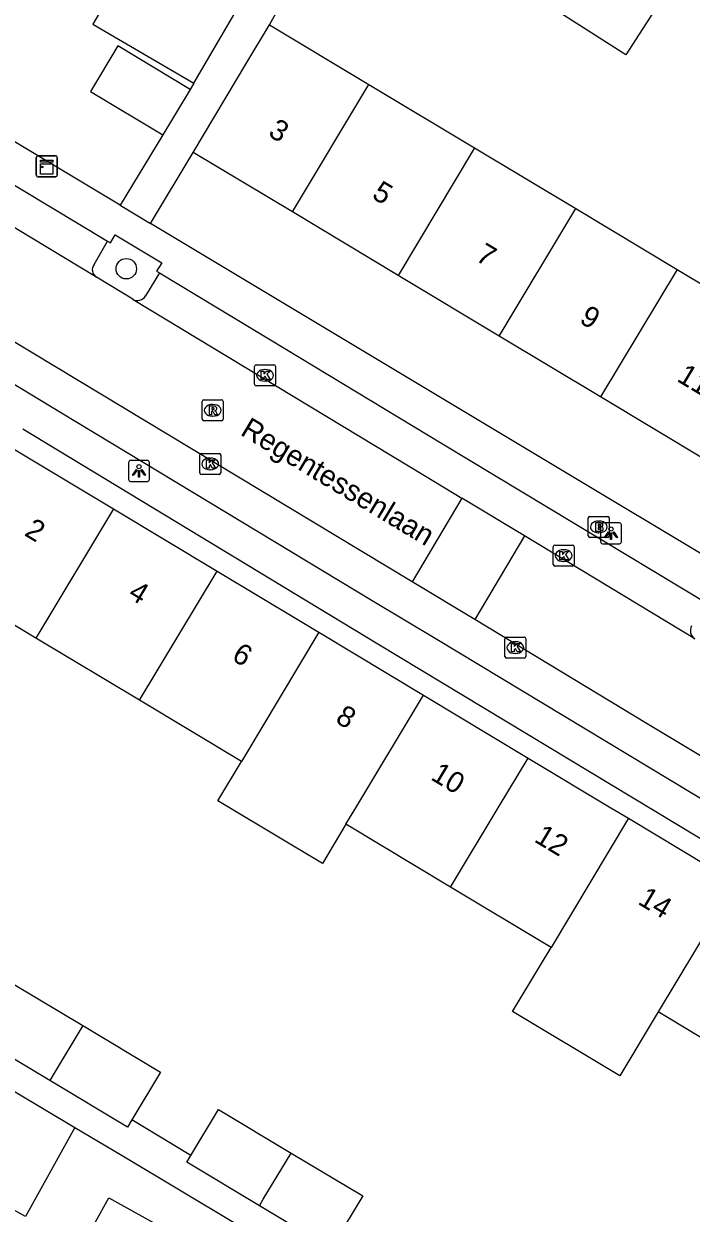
# Model space of a CAD drawing. Extents: x 160107 to 160928, y 382056 to 382918.
# Drawn here: x 160352.1 to 160383.9, y 382230.6 to 382287.4 of the extents above; entities that cross this region are included whole.
import ezdxf

# ---------------------------------------------------------------- set-up
doc = ezdxf.new("R2010")
doc.units = 0
for name, color, linetype in [('IMGEO_Boom', 7, 'Continuous'), ('IMGEO_Brandkraan', 7, 'Continuous'), ('IMGEO_Kast', 7, 'Continuous'), ('IMGEO_Kolk', 7, 'Continuous'), ('IMGEO_Lichtpunt', 7, 'Continuous'), ('IMGEO_Openbare_ruimte_label', 7, 'Continuous'), ('IMGEO_Pand', 7, 'Continuous'), ('IMGEO_Pand_nummerreeks', 7, 'Continuous'), ('IMGEO_Parkeervlak_open', 7, 'Continuous'), ('IMGEO_Rijbaan_lokaal_open', 7, 'Continuous'), ('IMGEO_Rioolput', 7, 'Continuous'), ('IMGEO_Voetpad_open', 7, 'Continuous')]:
    doc.layers.add(name, color=color, linetype=linetype)

msp = doc.modelspace()

# ---------------------------------------------------------------- linework, layer by layer
at = {"layer": 'IMGEO_Boom'}
msp.add_circle((160356.952, 382275.745), 0.489, dxfattribs=at)
at = {"layer": 'IMGEO_Brandkraan'}
for p, q in [((160379.024, 382262.989), (160379.024, 382263.841)), ((160379.099, 382263.915), (160379.951, 382263.915)), ((160380.025, 382263.841), (160380.025, 382262.989)), ((160379.512, 382263.695), (160379.537, 382263.695)), ((160379.951, 382262.915), (160379.099, 382262.915)), ((160379.535, 382263.135), (160379.51, 382263.135))]:
    msp.add_line(p, q, dxfattribs=at)
for points in [[(160379.024, 382262.989), (160379.024, 382263.841)], [(160379.099, 382263.915), (160379.951, 382263.915)], [(160380.025, 382263.841), (160380.025, 382262.989)], [(160379.372, 382263.615), (160379.372, 382263.215), (160379.585, 382263.215)], [(160379.603, 382263.615), (160379.372, 382263.615)], [(160379.551, 382263.534), (160379.497, 382263.534), (160379.497, 382263.458)], [(160379.497, 382263.458), (160379.55, 382263.458)], [(160379.559, 382263.382), (160379.497, 382263.382), (160379.497, 382263.301)], [(160379.497, 382263.301), (160379.559, 382263.301)], [(160379.951, 382262.915), (160379.099, 382262.915)]]:
    msp.add_lwpolyline(points, dxfattribs=at)
for centre, radius, start, end in [((160379.101, 382263.839), 0.0765, 91.552, 178.448), ((160379.101, 382263.839), 0.0765, 91.552, 178.448), ((160379.949, 382263.839), 0.0765, 1.552, 88.448), ((160379.949, 382263.839), 0.0765, 1.552, 88.448), ((160379.552, 382263.496), 0.0379, 267.8285, 90.9355), ((160379.56, 382263.341), 0.0404, 269.8759, 90.5077), ((160379.591, 382263.466), 0.251, 268.6676, 293.5347), ((160379.607, 382263.47), 0.145, 59.4692, 91.5367), ((160379.632, 382263.517), 0.0922, 285.5137, 58.1501), ((160379.637, 382263.325), 0.105, 301.3115, 78.989), ((160379.101, 382262.991), 0.0765, 181.552, 268.448), ((160379.101, 382262.991), 0.0765, 181.552, 268.448), ((160379.949, 382262.991), 0.0765, 271.552, 358.448), ((160379.949, 382262.991), 0.0765, 271.552, 358.448)]:
    msp.add_arc(centre, radius, start, end, dxfattribs=at)
for centre, major_axis, ratio, start_param, end_param in [((160379.511, 382263.415), (-0.387, 0.002), 0.722429, 4.712389, 7.853982), ((160379.536, 382263.415), (-0.39, 0.002), 0.717154, 1.570796, 4.712389)]:
    msp.add_ellipse(centre, major_axis=major_axis, ratio=ratio, start_param=start_param, end_param=end_param, dxfattribs=at)
at = {"layer": 'IMGEO_Kast'}
for p, q in [((160352.654, 382280.212), (160352.654, 382281.053)), ((160352.654, 382281.053), (160352.654, 382280.212)), ((160352.729, 382281.137), (160353.57, 382281.137)), ((160353.57, 382281.137), (160352.729, 382281.137)), ((160353.654, 382281.062), (160353.654, 382280.221)), ((160353.654, 382280.221), (160353.654, 382281.062)), ((160353.579, 382280.137), (160352.738, 382280.137)), ((160352.738, 382280.137), (160353.579, 382280.137))]:
    msp.add_line(p, q, dxfattribs=at)
for points in [[(160352.849, 382280.927), (160353.449, 382280.927), (160353.449, 382280.842), (160352.849, 382280.842), (160352.849, 382280.927)], [(160352.849, 382280.752), (160353.449, 382280.752), (160353.449, 382280.263), (160352.849, 382280.263), (160352.849, 382280.752)]]:
    msp.add_lwpolyline(points, dxfattribs=at)
msp.add_circle((160352.933, 382280.601), 0.0377, dxfattribs=at)
for centre, start, end in [((160352.732, 382281.059), 92.4484, 184.2845), ((160352.732, 382281.059), 92.4484, 184.2845), ((160353.576, 382281.059), 2.4484, 94.2845), ((160353.576, 382281.059), 2.4484, 94.2845), ((160352.732, 382280.215), 182.4484, 274.2845), ((160352.732, 382280.215), 182.4484, 274.2845), ((160353.576, 382280.215), 272.4484, 4.2845), ((160353.576, 382280.215), 272.4484, 4.2845)]:
    msp.add_arc(centre, 0.0779, start, end, dxfattribs=at)
at = {"layer": 'IMGEO_Kolk'}
for p, q in [((160363.155, 382271.154), (160364.007, 382271.154)), ((160363.08, 382270.228), (160363.08, 382271.08)), ((160363.568, 382270.934), (160363.593, 382270.934)), ((160364.081, 382271.08), (160364.081, 382270.228)), ((160364.007, 382270.154), (160363.155, 382270.154)), ((160363.591, 382270.374), (160363.566, 382270.374)), ((160360.462, 382265.998), (160360.462, 382266.85)), ((160360.537, 382266.924), (160361.389, 382266.924)), ((160360.95, 382266.704), (160360.975, 382266.704)), ((160361.463, 382266.85), (160361.463, 382265.998)), ((160360.973, 382266.144), (160360.948, 382266.144)), ((160361.389, 382265.924), (160360.537, 382265.924)), ((160377.348, 382261.616), (160377.348, 382262.468)), ((160377.423, 382262.542), (160378.275, 382262.542)), ((160377.836, 382262.322), (160377.861, 382262.322)), ((160378.349, 382262.468), (160378.349, 382261.616)), ((160378.275, 382261.542), (160377.423, 382261.542)), ((160377.859, 382261.762), (160377.834, 382261.762)), ((160375.038, 382257.221), (160375.038, 382258.073)), ((160375.113, 382258.147), (160375.965, 382258.147)), ((160376.039, 382258.073), (160376.039, 382257.221)), ((160375.526, 382257.927), (160375.551, 382257.927)), ((160375.965, 382257.147), (160375.113, 382257.147)), ((160375.549, 382257.367), (160375.524, 382257.367))]:
    msp.add_line(p, q, dxfattribs=at)
for points in [[(160363.155, 382271.154), (160364.007, 382271.154)], [(160363.08, 382270.228), (160363.08, 382271.08)], [(160363.401, 382270.854), (160363.524, 382270.854), (160363.524, 382270.703), (160363.654, 382270.854), (160363.818, 382270.854), (160363.672, 382270.703), (160363.825, 382270.454), (160363.673, 382270.454), (160363.588, 382270.618), (160363.524, 382270.551), (160363.524, 382270.454), (160363.401, 382270.454), (160363.401, 382270.854)], [(160364.081, 382271.08), (160364.081, 382270.228)], [(160364.007, 382270.154), (160363.155, 382270.154)], [(160360.462, 382265.998), (160360.462, 382266.85)], [(160360.537, 382266.924), (160361.389, 382266.924)], [(160360.783, 382266.624), (160360.906, 382266.624), (160360.906, 382266.473), (160361.036, 382266.624), (160361.2, 382266.624), (160361.054, 382266.473), (160361.207, 382266.224), (160361.055, 382266.224), (160360.97, 382266.388), (160360.906, 382266.321), (160360.906, 382266.224), (160360.783, 382266.224), (160360.783, 382266.624)], [(160361.463, 382266.85), (160361.463, 382265.998)], [(160361.389, 382265.924), (160360.537, 382265.924)], [(160377.348, 382261.616), (160377.348, 382262.468)], [(160377.423, 382262.542), (160378.275, 382262.542)], [(160377.669, 382262.242), (160377.792, 382262.242), (160377.792, 382262.091), (160377.922, 382262.242), (160378.086, 382262.242), (160377.94, 382262.091), (160378.093, 382261.842), (160377.941, 382261.842), (160377.856, 382262.006), (160377.792, 382261.939), (160377.792, 382261.842), (160377.669, 382261.842), (160377.669, 382262.242)], [(160378.349, 382262.468), (160378.349, 382261.616)], [(160378.275, 382261.542), (160377.423, 382261.542)], [(160375.038, 382257.221), (160375.038, 382258.073)], [(160375.113, 382258.147), (160375.965, 382258.147)], [(160376.039, 382258.073), (160376.039, 382257.221)], [(160375.359, 382257.847), (160375.482, 382257.847), (160375.482, 382257.696), (160375.612, 382257.847), (160375.776, 382257.847), (160375.63, 382257.696), (160375.783, 382257.447), (160375.631, 382257.447), (160375.546, 382257.611), (160375.482, 382257.544), (160375.482, 382257.447), (160375.359, 382257.447), (160375.359, 382257.847)], [(160375.965, 382257.147), (160375.113, 382257.147)]]:
    msp.add_lwpolyline(points, dxfattribs=at)
for centre, start, end in [((160363.157, 382271.078), 91.552, 178.448), ((160363.157, 382271.078), 91.552, 178.448), ((160364.005, 382271.078), 1.552, 88.448), ((160364.005, 382271.078), 1.552, 88.448), ((160363.157, 382270.23), 181.552, 268.448), ((160363.157, 382270.23), 181.552, 268.448), ((160364.005, 382270.23), 271.552, 358.448), ((160364.005, 382270.23), 271.552, 358.448), ((160360.539, 382266.848), 91.552, 178.448), ((160360.539, 382266.848), 91.552, 178.448), ((160361.387, 382266.848), 1.552, 88.448), ((160361.387, 382266.848), 1.552, 88.448), ((160360.539, 382266), 181.552, 268.448), ((160360.539, 382266), 181.552, 268.448), ((160361.387, 382266), 271.552, 358.448), ((160361.387, 382266), 271.552, 358.448), ((160377.425, 382262.466), 91.552, 178.448), ((160377.425, 382262.466), 91.552, 178.448), ((160378.273, 382262.466), 1.552, 88.448), ((160378.273, 382262.466), 1.552, 88.448), ((160377.425, 382261.618), 181.552, 268.448), ((160377.425, 382261.618), 181.552, 268.448), ((160378.273, 382261.618), 271.552, 358.448), ((160378.273, 382261.618), 271.552, 358.448), ((160375.115, 382258.071), 91.552, 178.448), ((160375.115, 382258.071), 91.552, 178.448), ((160375.963, 382258.071), 1.552, 88.448), ((160375.963, 382258.071), 1.552, 88.448), ((160375.115, 382257.223), 181.552, 268.448), ((160375.115, 382257.223), 181.552, 268.448), ((160375.963, 382257.223), 271.552, 358.448), ((160375.963, 382257.223), 271.552, 358.448)]:
    msp.add_arc(centre, 0.0765, start, end, dxfattribs=at)
for centre, major_axis, ratio, start_param, end_param in [((160363.567, 382270.654), (-0.387, 0.002), 0.722429, 4.712389, 7.853982), ((160363.592, 382270.654), (-0.39, 0.002), 0.717154, 1.570796, 4.712389), ((160360.949, 382266.424), (-0.387, 0.002), 0.722429, 4.712389, 7.853982), ((160360.974, 382266.424), (-0.39, 0.002), 0.717154, 1.570796, 4.712389), ((160377.835, 382262.042), (-0.387, 0.002), 0.722429, 4.712389, 7.853982), ((160377.86, 382262.042), (-0.39, 0.002), 0.717154, 1.570796, 4.712389), ((160375.525, 382257.647), (-0.387, 0.002), 0.722429, 4.712389, 7.853982), ((160375.55, 382257.647), (-0.39, 0.002), 0.717154, 1.570796, 4.712389)]:
    msp.add_ellipse(centre, major_axis=major_axis, ratio=ratio, start_param=start_param, end_param=end_param, dxfattribs=at)
at = {"layer": 'IMGEO_Lichtpunt'}
for p, q in [((160357.965, 382266.586), (160357.157, 382266.586)), ((160357.965, 382266.586), (160357.157, 382266.586)), ((160357.063, 382266.491), (160357.063, 382265.684)), ((160357.063, 382266.491), (160357.063, 382265.684)), ((160358.059, 382265.684), (160358.059, 382266.491)), ((160358.059, 382265.684), (160358.059, 382266.491)), ((160357.157, 382265.59), (160357.965, 382265.59)), ((160357.157, 382265.59), (160357.965, 382265.59)), ((160379.613, 382263.513), (160379.613, 382262.706)), ((160379.613, 382263.513), (160379.613, 382262.706)), ((160380.515, 382263.608), (160379.707, 382263.608)), ((160380.515, 382263.608), (160379.707, 382263.608)), ((160380.609, 382262.706), (160380.609, 382263.513)), ((160380.609, 382262.706), (160380.609, 382263.513)), ((160379.707, 382262.612), (160380.515, 382262.612)), ((160379.707, 382262.612), (160380.515, 382262.612))]:
    msp.add_line(p, q, dxfattribs=at)
for points in [[(160357.437, 382266.155), (160357.476, 382266.127), (160357.288, 382265.865), (160357.25, 382265.892), (160357.437, 382266.155)], [(160357.539, 382266.107), (160357.586, 382266.107), (160357.586, 382265.785), (160357.539, 382265.785), (160357.539, 382266.107)], [(160357.649, 382266.127), (160357.687, 382266.154), (160357.874, 382265.892), (160357.835, 382265.864), (160357.649, 382266.127)], [(160379.987, 382263.177), (160380.026, 382263.149), (160379.838, 382262.887), (160379.8, 382262.914), (160379.987, 382263.177)], [(160380.199, 382263.149), (160380.237, 382263.176), (160380.424, 382262.914), (160380.385, 382262.886), (160380.199, 382263.149)], [(160380.089, 382263.129), (160380.136, 382263.129), (160380.136, 382262.807), (160380.089, 382262.807), (160380.089, 382263.129)]]:
    msp.add_lwpolyline(points, dxfattribs=at)
for centre in [(160357.562, 382266.289), (160380.112, 382263.311)]:
    msp.add_circle(centre, 0.0994, dxfattribs=at)
for centre, start, end in [((160357.157, 382266.491), 90, 180), ((160357.157, 382266.491), 90, 180), ((160357.965, 382266.491), 0, 90), ((160357.965, 382266.491), 0, 90), ((160357.157, 382265.684), 180, 270), ((160357.157, 382265.684), 180, 270), ((160357.965, 382265.684), 270, 0), ((160357.965, 382265.684), 270, 360), ((160379.707, 382263.513), 90, 180), ((160379.707, 382263.513), 90, 180), ((160380.515, 382263.513), 0, 90), ((160380.515, 382263.513), 0, 90), ((160379.707, 382262.706), 180, 270), ((160379.707, 382262.706), 180, 270), ((160380.515, 382262.706), 270, 0), ((160380.515, 382262.706), 270, 360)]:
    msp.add_arc(centre, 0.0946, start, end, dxfattribs=at)
at = {"layer": 'IMGEO_Pand'}
for points in [[(160362.134, 382287.959), (160357.305, 382290.773), (160355.353, 382287.424), (160360.175, 382284.614)], [(160383.854, 382290.698), (160380.822, 382285.961), (160377.525, 382288.071), (160379.001, 382290.4), (160378.944, 382290.437)], [(160360.175, 382284.614), (160362.134, 382287.959)], [(160360.142, 382281.302), (160362.714, 382285.59), (160363.795, 382287.392)], [(160363.795, 382287.392), (160368.538, 382284.547)], [(160359.999, 382284.313), (160356.54, 382286.388), (160355.236, 382284.213), (160358.695, 382282.138)], [(160359.999, 382284.313), (160358.695, 382282.138)], [(160364.885, 382278.457), (160368.538, 382284.547)], [(160368.538, 382284.547), (160373.592, 382281.515)], [(160373.592, 382281.515), (160369.939, 382275.425)], [(160373.592, 382281.515), (160378.424, 382278.617)], [(160364.885, 382278.457), (160360.142, 382281.302)], [(160374.771, 382272.527), (160378.424, 382278.617)], [(160378.424, 382278.617), (160383.267, 382275.712)], [(160369.939, 382275.425), (160364.885, 382278.457)], [(160383.267, 382275.712), (160379.614, 382269.622)], [(160383.267, 382275.712), (160388.295, 382272.696)], [(160374.771, 382272.527), (160369.939, 382275.425)], [(160379.614, 382269.622), (160374.771, 382272.527)], [(160384.642, 382266.606), (160379.614, 382269.622)], [(160351.487, 382267.189), (160356.34, 382264.274)], [(160356.34, 382264.274), (160352.635, 382258.104)], [(160356.34, 382264.274), (160361.286, 382261.304)], [(160352.635, 382258.104), (160347.79, 382261.014)], [(160357.581, 382255.134), (160361.286, 382261.304)], [(160361.286, 382261.304), (160366.156, 382258.379)], [(160357.581, 382255.134), (160352.635, 382258.104)], [(160366.156, 382258.379), (160362.451, 382252.209)], [(160366.156, 382258.379), (160371.151, 382255.379)], [(160367.446, 382249.209), (160367.921, 382250), (160371.151, 382255.379)], [(160371.151, 382255.379), (160376.151, 382252.375)], [(160362.451, 382252.209), (160357.581, 382255.134)], [(160372.446, 382246.206), (160374.724, 382250), (160376.151, 382252.375)], [(160376.151, 382252.375), (160380.106, 382250), (160380.949, 382249.494)], [(160367.446, 382249.209), (160366.319, 382247.333), (160361.878, 382250), (160361.324, 382250.333), (160362.451, 382252.209)], [(160372.446, 382246.206), (160367.446, 382249.209)], [(160380.949, 382249.494), (160377.243, 382243.325)], [(160380.949, 382249.494), (160386.067, 382246.42)], [(160377.243, 382243.325), (160372.446, 382246.206)], [(160386.067, 382246.42), (160382.362, 382240.25)], [(160382.362, 382240.25), (160380.524, 382237.191), (160375.405, 382240.266), (160377.243, 382243.325)], [(160350.155, 382239.337), (160351.52, 382241.611), (160354.874, 382239.597)], [(160387.122, 382237.392), (160382.362, 382240.25)], [(160353.294, 382236.966), (160349.94, 382238.98), (160350.155, 382239.337)], [(160354.874, 382239.597), (160354.83, 382239.523), (160353.507, 382237.321), (160353.294, 382236.966)], [(160354.874, 382239.597), (160358.585, 382237.368), (160357.215, 382235.087)], [(160350.245, 382237.256), (160354.49, 382234.732)], [(160357.215, 382235.087), (160357.005, 382234.737), (160353.294, 382236.966)], [(160360.039, 382233.387), (160361.362, 382235.59), (160364.821, 382233.506)], [(160354.49, 382234.732), (160352.129, 382230.47), (160349.972, 382231.666), (160347.333, 382226.903), (160350.081, 382225.38)], [(160363.308, 382230.987), (160359.846, 382233.066), (160360.039, 382233.387)], [(160363.308, 382230.987), (160363.498, 382231.303), (160364.821, 382233.506)], [(160364.821, 382233.506), (160368.249, 382231.454), (160366.921, 382229.242)], [(160350.081, 382225.38), (160352.161, 382224.228), (160354.813, 382229.016), (160356.116, 382231.368), (160358.55, 382230.019)], [(160366.921, 382229.242), (160366.734, 382228.93), (160363.308, 382230.987)]]:
    msp.add_lwpolyline(points, dxfattribs=at)
at = {"layer": 'IMGEO_Parkeervlak_open'}
for points in [[(160355.411, 382275.949), (160356.055, 382277.065)], [(160358.536, 382275.545), (160357.868, 382274.448)]]:
    msp.add_lwpolyline(points, dxfattribs=at)
for centre, radius, start, end in [((160355.744, 382275.7), 0.416, 143.198, 238.3968), ((160357.485, 382274.669), 0.442, 239.2316, 330.0331), ((160384.379, 382258.461), 0.481, 151.9628, 235.502)]:
    msp.add_arc(centre, radius, start, end, dxfattribs=at)
at = {"layer": 'IMGEO_Rijbaan_lokaal_open'}
for points in [[(160355.526, 382275.346), (160355.493, 382275.363), (160349.36, 382279.058)], [(160357.259, 382274.289), (160355.526, 382275.346)], [(160370.614, 382260.795), (160363.396, 382265.134), (160346.971, 382275.028)], [(160357.259, 382274.289), (160357.276, 382274.276), (160364.164, 382270.125), (160371.204, 382265.869), (160372.99, 382264.789)], [(160372.99, 382264.789), (160370.614, 382260.795)], [(160375.974, 382262.984), (160372.99, 382264.789)], [(160375.974, 382262.984), (160373.597, 382258.998)], [(160384.107, 382258.065), (160375.974, 382262.984)], [(160373.597, 382258.998), (160370.614, 382260.795)], [(160402.764, 382241.416), (160397.115, 382244.844), (160381.838, 382254.013), (160373.597, 382258.998)]]:
    msp.add_lwpolyline(points, dxfattribs=at)
at = {"layer": 'IMGEO_Rioolput'}
for p, q in [((160360.58, 382268.557), (160360.58, 382269.409)), ((160360.655, 382269.483), (160361.507, 382269.483)), ((160361.581, 382269.409), (160361.581, 382268.557)), ((160361.068, 382269.263), (160361.093, 382269.263)), ((160361.507, 382268.483), (160360.655, 382268.483)), ((160361.091, 382268.703), (160361.066, 382268.703))]:
    msp.add_line(p, q, dxfattribs=at)
for points in [[(160360.58, 382268.557), (160360.58, 382269.409)], [(160360.655, 382269.483), (160361.507, 382269.483)], [(160361.581, 382269.409), (160361.581, 382268.557)], [(160361.169, 382269.181), (160360.917, 382269.183), (160360.917, 382268.783)], [(160360.917, 382268.783), (160361.041, 382268.783), (160361.041, 382268.945), (160361.052, 382268.945)], [(160361.095, 382269.102), (160361.041, 382269.102), (160361.041, 382269.021)], [(160361.041, 382269.021), (160361.093, 382269.021)], [(160361.099, 382268.916), (160361.17, 382268.783), (160361.31, 382268.783), (160361.245, 382268.909)], [(160361.507, 382268.483), (160360.655, 382268.483)]]:
    msp.add_lwpolyline(points, dxfattribs=at)
for centre, radius, start, end in [((160360.657, 382269.407), 0.0765, 91.552, 178.448), ((160360.657, 382269.407), 0.0765, 91.552, 178.448), ((160361.505, 382269.407), 0.0765, 1.552, 88.448), ((160361.505, 382269.407), 0.0765, 1.552, 88.448), ((160361.051, 382268.892), 0.0533, 26.0293, 88.6989), ((160361.077, 382269.21), 0.19, 274.7715, 282.9687), ((160361.101, 382269.006), 0.0964, 77.0061, 93.1865), ((160361.115, 382269.063), 0.0378, 276.6634, 79.6772), ((160361.168, 382269.071), 0.109, 350.3612, 89.416), ((160361.166, 382269.071), 0.112, 277.5842, 350.9817), ((160361.15, 382268.856), 0.108, 29.5134, 73.7905), ((160360.657, 382268.559), 0.0765, 181.552, 268.448), ((160360.657, 382268.559), 0.0765, 181.552, 268.448), ((160361.505, 382268.559), 0.0765, 271.552, 358.448), ((160361.505, 382268.559), 0.0765, 271.552, 358.448)]:
    msp.add_arc(centre, radius, start, end, dxfattribs=at)
for centre, major_axis, ratio, start_param, end_param in [((160361.067, 382268.983), (-0.387, 0.002), 0.722429, 4.712389, 7.853982), ((160361.092, 382268.983), (-0.39, 0.002), 0.717154, 1.570796, 4.712389)]:
    msp.add_ellipse(centre, major_axis=major_axis, ratio=ratio, start_param=start_param, end_param=end_param, dxfattribs=at)
at = {"layer": 'IMGEO_Voetpad_open'}
for points in [[(160363.795, 382287.392), (160369.034, 382296.857)], [(160356.664, 382278.779), (160344.039, 382286.352)], [(160360.175, 382284.614), (160359.999, 382284.313)], [(160358.695, 382282.138), (160356.664, 382278.779)], [(160358.109, 382277.912), (160360.142, 382281.302)], [(160350.59, 382280.346), (160356.055, 382277.065)], [(160356.664, 382278.779), (160358.109, 382277.912)], [(160356.055, 382277.065), (160356.19, 382276.984), (160356.427, 382277.363), (160358.645, 382276.022), (160358.401, 382275.626), (160358.536, 382275.545)], [(160407.669, 382248.188), (160404.646, 382250), (160358.109, 382277.912)], [(160358.536, 382275.545), (160363.843, 382272.35), (160372.063, 382267.382), (160384.647, 382259.799)], [(160346.443, 382273.357), (160353.864, 382268.87), (160368.706, 382259.906), (160371.786, 382258.051), (160387.002, 382248.878), (160392.646, 382245.482), (160401.49, 382240.126), (160401.767, 382240.616)], [(160401.443, 382238.222), (160387.269, 382246.785), (160368.972, 382257.814), (160352.016, 382268.075)], [(160360.039, 382233.387), (160358.501, 382234.313), (160357.215, 382235.087)], [(160354.49, 382234.732), (160356.752, 382233.387), (160373.273, 382223.501)]]:
    msp.add_lwpolyline(points, dxfattribs=at)

# ---------------------------------------------------------------- texts
at = {"layer": 'IMGEO_Openbare_ruimte_label'}
msp.add_text('Regentessenlaan', height=1, rotation=328.9969, dxfattribs=at).set_placement((160362.354, 382267.836))
at = {"layer": 'IMGEO_Pand_nummerreeks'}
for s, rotation, p in [('3', 329.0424, (160363.68, 382282.119)), ('5', 329.0424, (160368.635, 382279.146)), ('7', 329.0424, (160373.591, 382276.173)), ('9', 329.0424, (160378.547, 382273.2)), ('11', 329.0424, (160383.206, 382270.405)), ('2', 329.0102, (160352.035, 382263.033)), ('4', 329.0102, (160356.987, 382260.059)), ('6', 329.0102, (160361.937, 382257.086)), ('8', 329.0102, (160366.889, 382254.111)), ('10', 329.0102, (160371.445, 382251.375)), ('12', 329.0102, (160376.39, 382248.405)), ('14', 329.0102, (160381.342, 382245.43))]:
    msp.add_text(s, height=1, rotation=rotation, dxfattribs=at).set_placement(p)

doc.saveas('drawing.dxf')
